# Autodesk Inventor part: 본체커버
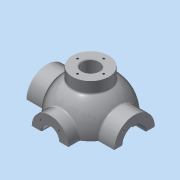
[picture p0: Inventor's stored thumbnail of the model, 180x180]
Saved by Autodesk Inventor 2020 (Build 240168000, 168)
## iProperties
Created: 2015-12
Part Number: 본체커버
Material: 알루미늄 6061
Document SubType Name: Modeling
Designer: mduedu
Density: 2.71 g/cm^3
Mass: 574.083 g
Surface Area: 451.737 cm^2
Volume: 211.839 cm^3
Appearance: 알루미늄 - 평지
Author: mduedu
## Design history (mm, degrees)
sketch "스케치1"
  geometry: L1 (-53, 0)-(53, 0); A1 r 53 centre (0, 0) between (53, 0) and (-53, 0); 2 further points
  constraints: 2 coincident, 2 end point, 2 point on circle, 1 centre point, 1 horizontal, 1 midpoint
  dimensions: "d0" = 53 radius of A1
revolve "회전1" sketch "스케치1" stored, may be unused: angle "d2" = 90 deg
feature "쉘1" dims "d11" = 10
node "작업 평면1"
sketch "스케치2"
  geometry: C1 r 31 at (0, 0); 1 further point
  constraints: 1 centre point, 1 coincident
  dimensions: "d4" = 62 diameter of C1
extrude "돌출1" join sketch "스케치2" stored distance "d5" = 10; taper "d6" = 0 deg
node "작업 평면2"
sketch "스케치3"
  geometry: C1 r 28 at (0, 0); 1 further point
  constraints: 1 centre point, 1 coincident
  dimensions: "d8" = 56 diameter of C1
extrude "돌출2" join sketch "스케치3" stored distance "d9" = 10; taper "d10" = 0 deg
hole "구멍1" diameter "d14" = 35; stored, may be unused: countersink angle "d18" = 90 deg, drill point angle "d20" = 0 deg; dims "d12" = 10, "d13" = 10, "d15" = 6, "d16" = 4, "d17" = 2, "d19" = 16
hole "구멍2" diameter "d23" = 27; stored, may be unused: countersink angle "d27" = 90 deg, drill point angle "d29" = 0 deg; dims "d21" = 10, "d22" = 10, "d24" = 6, "d25" = 4, "d26" = 2, "d28" = 16
fillet "모깎기1" dims "d30" = 0.3
hole "구멍3" diameter "d33" = 26; stored, may be unused: countersink angle "d37" = 90 deg, drill point angle "d39" = 0 deg; dims "d31" = 10, "d32" = 10, "d34" = 6, "d35" = 4, "d36" = 2, "d38" = 16
chamfer "모따기1" distance "d40" = 1; stored, may be unused: second distance "d41" = 2, angle "d42" = 45 deg
sketch "스케치4"
  geometry: L1 (0, 0)-(0, -25); L2 (0, 0)-(-17.678, -17.678); A1 r 25 centre (0, 0) between (-17.678, -17.678) and (0, -25); 1 further point
  constraints: 4 end point, 2 point on circle, 1 centre point, 1 coincident, 1 vertical
  dimensions: "d43" = 50 diameter of A1; "d47" = 45 deg angle of L1 L2
hole "구멍4" sketch "스케치4" at (-17.678, -17.678) diameter "d49" = 3.242; stored, may be unused: countersink angle "d53" = 90 deg, drill point angle "d55" = 118 deg; dims "d50" = 11, "d51" = 4, "d52" = 2, "d54" = 13
sketch "스케치5"
  geometry: L1 (0, 0)-(0, -20); L2 (0, 0)-(-14.142, -14.142); A1 r 20 centre (0, 0) between (0, -20) and (-14.142, -14.142); 2 further points
  constraints: 4 end point, 2 coincident, 2 point on circle, 1 centre point, 1 vertical
  dimensions: "d59" = 40 diameter of A1; "d65" = 45 deg angle of L1 L2
hole "구멍5" sketch "스케치5" at (-14.142, -14.142) diameter "d67" = 3.242; stored, may be unused: countersink angle "d71" = 90 deg, drill point angle "d73" = 118 deg; dims "d68" = 8, "d69" = 4, "d70" = 2, "d72" = 10
node "작업 평면3"
sketch "스케치6"
  geometry: C1 r 65 at (0, 0); 1 further point
  constraints: 1 centre point, 1 coincident
  dimensions: "d78" = 130 diameter of C1
extrude "돌출3" join sketch "스케치6" distance "d80" = 10; taper "d81" = 0 deg
sketch "스케치7"
  geometry: C1 r 20 at (0, 0); 1 further point
  constraints: 1 centre point, 1 coincident
  dimensions: "d82" = 40 diameter of C1
extrude "돌출4" join sketch "스케치7" stored distance "d84" = 10; taper "d85" = 0 deg
sketch "스케치8"
  geometry: 2 further points
  constraints: 1 coincident
hole "구멍6" sketch "스케치8" at (0, 0) diameter "d86" = 20; stored, may be unused: countersink angle "d90" = 90 deg, drill point angle "d92" = 118 deg; dims "d87" = 7, "d88" = 40, "d89" = 5, "d91" = 10
fillet "모깎기2" dims "d93" = 0.3
sketch "스케치9"
  geometry: L1 (65, -75)-(-65, -75) reference; L2 (-45, -75)-(-38.245, -36.692); A1 r 53 centre (0, 0) between (42.988, 31) and (42.988, -31) reference; 1 further point
  constraints: 2 end point, 1 point on circle, 1 point on line
  dimensions: "d94" = 45 horizontal distance of L2.start point (0, 0); "d95" = 80 deg angle of L2 L1
feature "리브1" sketch "스케치9" dims "d96" = 1, "d97" = 8, "d98" = 0, "d99" = 0, "d100" = 1, "d101" = 1
sketch "스케치10"
  geometry: L1 (0, 0)-(0, -55); L2 (0, 0)-(-38.891, -38.891); A1 r 55 centre (0, 0) between (0, -55) and (-38.891, -38.891); 2 further points
  constraints: 4 end point, 2 coincident, 2 point on circle, 1 centre point, 1 vertical
  dimensions: "d105" = 110 diameter of A1; "d107" = 45 deg angle of L1 L2
hole "구멍7" sketch "스케치10" at (-38.891, -38.891) diameter "d109" = 10; stored, may be unused: countersink angle "d113" = 90 deg, drill point angle "d115" = 118 deg; dims "d110" = 7, "d111" = 40, "d112" = 5, "d114" = 10
fillet "모깎기3" dims "d120" = 3
fillet "모깎기4" dims "d121" = 3, "d122" = 3
fillet "모깎기5" dims "d123" = 3
fillet "모깎기6" dims "d124" = 3
sketch "스케치11"
  geometry: C1 r 5 at (-38.891, 38.891) reference; C2 r 5 at (38.891, 38.891) reference; C3 r 5 at (38.891, -38.891) reference; C4 r 5 at (-38.891, -38.891) reference; C5 r 20 at (0, 0) reference; C6 r 65 at (0, 0) reference; 1 further point
  constraints: 3 other
feature "엠보싱1" sketch "스케치11" dims "d125" = 0.5, "d126" = 0
sketch "스케치12"
  geometry: L1 (0, 100)-(0, -100); L2 (0, 100)-(-150, 100); L3 (-150, 100)-(-150, -100); L4 (-150, -100)-(0, -100); 2 further points
  constraints: 8 end point, 3 perpendicular, 1 coincident, 1 midpoint, 1 vertical
  dimensions: "d127" = 200 distance of L2.end L3.end; "d129" = 150 distance of L3.end L1.end
extrude "돌출5" cut sketch "스케치12" extent not by distance; stored distance "d130" = 10; taper "d131" = 0 deg
sketch "스케치13"
  geometry: C1 r 7 at (0, -53); A1 r 53 centre (0, 0) between (-42.113, -32.179) and (42.113, -32.179) reference; 1 further point
  constraints: 1 centre point, 1 point on circle
  dimensions: "d132" = 14 diameter of C1
extrude "돌출6" join sketch "스케치13" distance "d133" = 5; taper "d134" = 0 deg
sketch "스케치14"
  geometry: C1 r 7 at (0, 0) reference; 1 further point
extrude "돌출7" cut sketch "스케치14" extent not by distance; stored distance "d135" = 5; taper "d136" = 0 deg
sketch "스케치15"
  geometry: C1 r 2.25 at (0, 53); A1 r 7 centre (0, 53) between (6.965, 52.302) and (-6.965, 52.302) reference; 1 further point
  constraints: 1 centre point, 1 coincident
  dimensions: "d139" = 4.5 diameter of C1
extrude "돌출8" cut sketch "스케치15" extent not by distance; stored distance "d141" = 5; taper "d142" = 0 deg
fillet "모깎기7" dims "d143" = 3
fillet "모깎기8" dims "d144" = 1
fillet "모깎기9" dims "d145" = 1
fillet "모깎기10" dims "d146" = 1
node "작업 평면4"
sketch "스케치16"
  geometry: C1 r 28 at (0, 0); 1 further point
  constraints: 1 centre point, 1 coincident
  dimensions: "d148" = 56 diameter of C1
extrude "돌출9" join sketch "스케치16" stored distance "d150" = 5; taper "d151" = 0 deg
hole "구멍8" diameter "d154" = 26; stored, may be unused: countersink angle "d158" = 90 deg, drill point angle "d160" = 118 deg; dims "d152" = 10, "d153" = 10, "d155" = 6, "d156" = 4, "d157" = 2, "d159" = 8
sketch "스케치17" dims "d161" = 40
  geometry: 3 further points
  constraints: 2 vertical alignment, 1 coincident, 2 other
hole "구멍9" sketch "스케치17" at (0, 20) diameter "d163" = 3.242; stored, may be unused: countersink angle "d167" = 90 deg, drill point angle "d169" = 118 deg; dims "d164" = 8, "d165" = 4, "d166" = 2, "d168" = 10
fillet "모깎기11" dims "d173" = 3
chamfer "모따기2" distance "d174" = 1; stored, may be unused: second distance "d175" = 2, angle "d176" = 45 deg
node "솔리드1"
mirror "대칭1"
mirror "대칭2"
pattern_circular "원형 패턴1" dims angle "d57" = 360 deg
mirror "대칭3"
pattern_circular "원형 패턴2" dims angle "d75" = 360 deg
pattern_circular "원형 패턴3" dims angle "d103" = 360 deg
pattern_circular "원형 패턴4" dims angle "d118" = 360 deg
pattern_circular "원형 패턴5" dims angle "d171" = 360 deg
node "투영된 루프1"
other parameters: "d3" = 67, "d7" = 62, "d77" = -85, "d147" = 62
